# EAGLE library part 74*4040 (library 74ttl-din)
12-bit asynchronous binary COUNTER
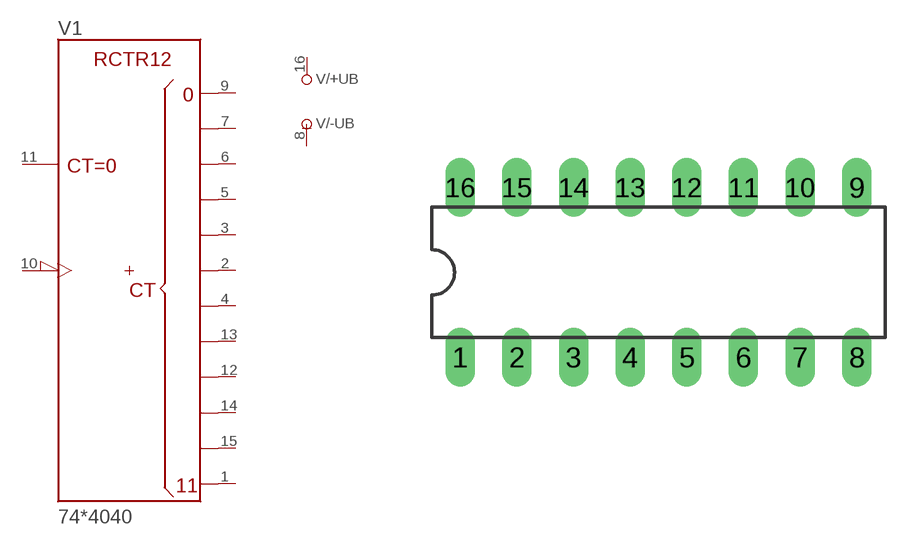
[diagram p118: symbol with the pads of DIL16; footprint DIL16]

Designator prefix V; gates /+UB=+UB /-UB=-UB 1=4040

## 744040N  [DIL16]
1  1:QL  out
2  1:QF  out
3  1:QE  out
4  1:QG  out
5  1:QD  out
6  1:QC  out
7  1:QB  out
8  /-UB:-UB  pwr
9  1:QA  out
10  1:CLK  in
11  1:CLR  in
12  1:QI  out
13  1:QH  out
14  1:QJ  out
15  1:QK  out
16  /+UB:+UB  pwr

## Footprint DIL16 (pad centres in mm)
Dual In Line Package
drill 0.813 long: 1 -8.89,-3.81; 2 -6.35,-3.81; 3 -3.81,-3.81; 4 -1.27,-3.81; 5 1.27,-3.81; 6 3.81,-3.81; 7 6.35,-3.81; 8 8.89,-3.81; 9 8.89,3.81; 10 6.35,3.81; 11 3.81,3.81; 12 1.27,3.81; 13 -1.27,3.81; 14 -3.81,3.81; 15 -6.35,3.81; 16 -8.89,3.81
